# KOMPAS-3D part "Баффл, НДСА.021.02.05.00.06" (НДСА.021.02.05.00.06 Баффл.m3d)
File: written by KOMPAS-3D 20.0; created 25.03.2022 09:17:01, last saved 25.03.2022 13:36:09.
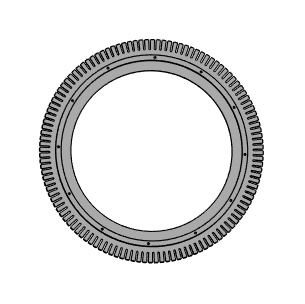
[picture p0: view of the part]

Document properties: Автор: adminzsc; Полное имя файла: C:\Users\vasilyeva\Desktop\НДСА.021.02.05.00.06 Баффл.m3d

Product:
- Part/product: Баффл  | designation НДСА.021.02.05.00.06
    Материал: АМг6  ГОСТ 4784-2019 (density 2640 kg/m3)
    Масса: 1.16448
    additional columns: <item xmlns="http://appius.ru/pdm" xmlns:xs="http://www.w3.org/2001/XMLSchema" x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; <item xmlns="http://appius.ru/pdm" xmlns:xs="http://www.w3.org/2001/XMLSchema" x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; <item xmlns="http://appius.ru/pdm" xmlns:xs="http://www.w3.org/2001/XMLSchema" x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
    source file: PM_APPIUS\НДСА.021.02.05.00.06 Баффл.cdw

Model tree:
1. Эскиз:1
2. Элемент выдавливания:1
     Расстояние 1 = 7
3. Эскиз:2  (with: Элемент выдавливания:1)
4. Элемент выдавливания:2
     Расстояние 1 = 7
5. Фаска:1  (with: Элемент выдавливания:2)
     Угол = 45; Длина 1 = 0.3; Длина 2 = 0.3
6. Фаска:2  (with: Элемент выдавливания:1)
     Угол = 20.2249; Длина 1 = 9.5; Длина 2 = 3.5
7. Скругление:1  (with: Элемент выдавливания:1, Фаска:2)
     Радиус = 0.2
8. Эскиз:3  (with: Элемент выдавливания:2)
9. Отверстие:1  (with: Элемент выдавливания:2)  (labels: M5)
     Глубина выреза = 10; Диаметр отверстия = 4.13397; Угол конуса дна = 118; Расстояние 2 = 168.5
10. M5  (with: Элемент выдавливания:2)  (labels: M5; cil0_24705-2004 coarse)
     Длина резьбы = 8; Шаг резьбы = 0.8; Номинальный диаметр резьбы = 5
11. Массив по концентрической сетке:1  (with: Отверстие:1)  (labels: M5)  (2 pattern instances)
12. Отверстие:1  (labels: M5)
13. Отверстие:1  (labels: M5)
14. Отверстие:1  (labels: M5)
15. Отверстие:1  (labels: M5)
16. Отверстие:1  (labels: M5)
17. Отверстие:1  (labels: M5)
18. Отверстие:1  (labels: M5)
19. Отверстие:1  (labels: M5)
20. Отверстие:1  (labels: M5)
21. Отверстие:1  (labels: M5)
22. Скругление:7  (with: Элемент выдавливания:1)
     Радиус = 0.5
23. Эскиз:6  (with: Элемент выдавливания:1)
24. Элемент выдавливания:4
     Расстояние 2 = 14
25. Скругление:8  (with: Элемент выдавливания:4)
     Радиус = 1.5
26. Массив по концентрической сетке:3  (with: Элемент выдавливания:4, Скругление:8)  (labels: АМг6  ГОСТ 4784-2019)  (120 pattern instances)
     Шаг 2 = 360

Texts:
  НДСА.021.02.05.00.06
